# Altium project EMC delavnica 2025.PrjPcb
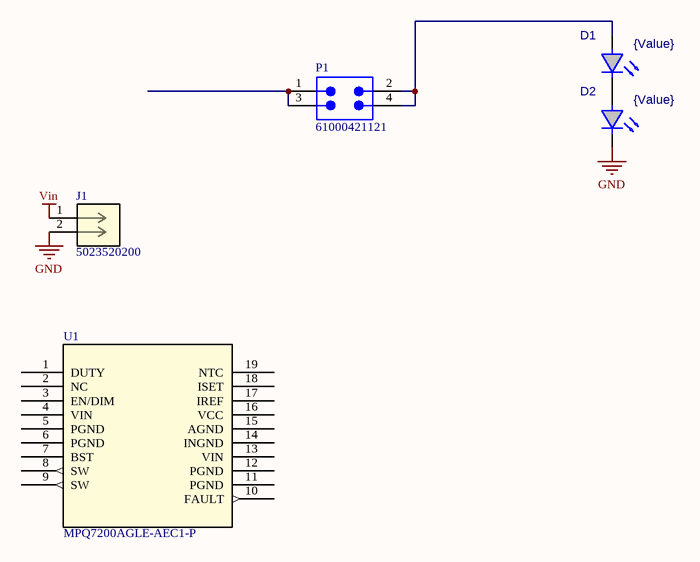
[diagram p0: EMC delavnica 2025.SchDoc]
1 sheet, 5 parts. Net scope: global (net labels, ports and power ports of the same name join across sheets).
Board file: EMC delavnica 2025.PcbDoc

## Sheet EMC delavnica 2025.SchDoc
size A4; SheetNumber: 1; SheetTotal: 1

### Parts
D1  value {Value}  [NFSW123G]  (hidden comment: NFSW123)
D2  value {Value}  [NFSW123G]  (hidden comment: NFSW123)
J1  5023520200  [CONN02_502352_MOL]
P1  61000421121  [61000421121]
U1  MPQ7200AGLE-AEC1-P  [QFN-19_MPQ7200A_MNP]

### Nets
GND: D2.K J1.2
Vin: J1.1
NetD1_A: D1.A P1.2 P1.4
NetD1_K: D1.K D2.A
NetP1_1: P1.1 P1.3

Not connected (* = marked no-connect by the designer): U1 1(DUTY) 2(NC) 3(EN/DIM) 4(VIN) 5(PGND) 6(PGND) 7(BST) 8(SW) 9(SW) 10(FAULT) 11(PGND) 12(PGND) 13(VIN) 14(INGND) 15(AGND) 16(VCC) 17(IREF) 18(ISET) 19(NTC)

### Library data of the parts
D1 D2 = NFSW123: Chip LED diode
J1 = 5023520200: No Description Available; Mfr_Name: Molex Connector Corporation
P1 = CMP-1502-01021-3: NexarPartId: 32855426; Row Spacing: 2.54mm; Gender: Male; Number of Contacts: 4; Connector Type: Male Pin; Contact Resistance: 20mΩ; Current Rating: 3A; Operating Supply Voltage: 250V
U1 = MPQ7200AGLE-AEC1-P: No Description Available; Mfr_Name: Monolithic Power Systems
